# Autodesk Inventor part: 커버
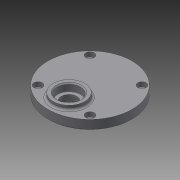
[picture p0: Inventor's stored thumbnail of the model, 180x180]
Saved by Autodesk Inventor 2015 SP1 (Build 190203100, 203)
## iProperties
Created: 2014-12
Part Number: 커버
Material: 일반
Document SubType Name: Modeling
Designer: kjc
Density: 1 g/cm^3
Appearance: 기본값
Mass: 42.0163 g
Surface Area: 144.996 cm^2
Volume: 42.0163 cm^3
Author: kjc
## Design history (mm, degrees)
sketch "스케치1"
  geometry: C1 r 40 at (0, 0); C2 r 7.5 at (0, -20); 1 further point
  constraints: 2 centre point, 1 coincident, 1 vertical alignment
  dimensions: "d0" = 80 diameter of C1; "d1" = 15 diameter of C2; "d2" = 20 distance of C2.centre point (0, 0)
extrude "돌출1" new body sketch "스케치1" distance "d3" = 9; taper "d4" = 0 deg
sketch "스케치2"
  geometry: C1 r 7.5 at (0, -20) reference; C2 r 15 at (0, -20)
  constraints: 1 centre point, 1 coincident
  dimensions: "d5" = 30 diameter of C2
extrude "돌출2" join sketch "스케치2" distance "d6" = 4; taper "d7" = 0 deg
sketch "스케치3"
  geometry: C1 r 7.5 at (0, 0) reference; C2 r 15 at (0, 0) reference; C3 r 11 at (0, 0); 1 further point
  constraints: 1 centre point, 1 coincident
  dimensions: "d8" = 22 diameter of C3
extrude "돌출3" cut sketch "스케치3" distance "d9" = 7; taper "d10" = 0 deg
sketch "스케치4"
  geometry: C1 r 7.5 at (0, -20) reference; C2 r 40 at (0, 0) reference; C3 r 14 at (0, 11); C4 r 14 at (0, -20)
  constraints: 2 centre point, 1 coincident, 1 vertical alignment
  dimensions: "d11" = 28 diameter of C3; "d12" = 28 diameter of C4; "d13" = 11 distance of C2.centre C3.centre
extrude "돌출4" join sketch "스케치4" distance "d14" = 3; taper "d15" = 0 deg
sketch "스케치5"
  geometry: C1 r 7.5 at (0, 0) reference; C2 r 14 at (0, 0) reference; C3 r 11 at (0, 0); 1 further point
  constraints: 1 centre point, 1 coincident
  dimensions: "d16" = 22 diameter of C3
extrude "돌출5" cut sketch "스케치5" distance "d17" = 7; taper "d18" = 0 deg
sketch "스케치6"
  geometry: C1 r 14 at (0, 0) reference; C2 r 11 at (0, 0); 1 further point
  constraints: 1 centre point, 1 coincident
  dimensions: "d19" = 22 diameter of C2
extrude "돌출6" cut sketch "스케치6" distance "d20" = 7; taper "d21" = 0 deg
chamfer "모따기1" distance "d22" = 1; stored, may be unused: second distance "d23" = 2, angle "d24" = 45 deg
fillet "모깎기1" dims "d25" = 2
sketch "스케치7"
  geometry: C1 r 9 at (0, 0); 2 further points
  constraints: 1 centre point, 1 coincident, 1 vertical alignment
  dimensions: "d26" = 18 diameter of C1
extrude "돌출7" cut sketch "스케치7" distance "d27" = 1; taper "d28" = 0 deg
fillet "모깎기2" dims "d29" = 0.3
chamfer "모따기2" distance "d30" = 1; stored, may be unused: second distance "d31" = 2, angle "d32" = 45 deg
fillet "모깎기3" dims "d33" = 1
sketch "스케치8"
  geometry: L1 (-35, 0)-(35, 0); L2 (24.749, 24.749)-(0, 0); C1 r 40 at (0, 0) reference; A1 r 35 centre (0, 0) between (24.749, 24.749) and (-35, 0); 3 further points
  constraints: 4 end point, 3 point on circle, 1 centre point, 1 coincident, 1 horizontal, 5 other
  dimensions: "d34" = 70 diameter of A1; "d35" = 45 deg angle of L1 L2; "d38" = 360 deg dimension on C1.centre L2.start (derived)
hole "구멍1" sketch "스케치8" at (24.749, 24.749), (-24.749, 24.749), (-24.749, -24.749), (24.749, -24.749) diameter "d40" = 4.5; stored, may be unused: countersink angle "d44" = 90 deg, drill point angle "d46" = 118 deg; dims "d41" = 6, "d42" = 8, "d43" = 4.4, "d45" = 8
node "솔리드1"
